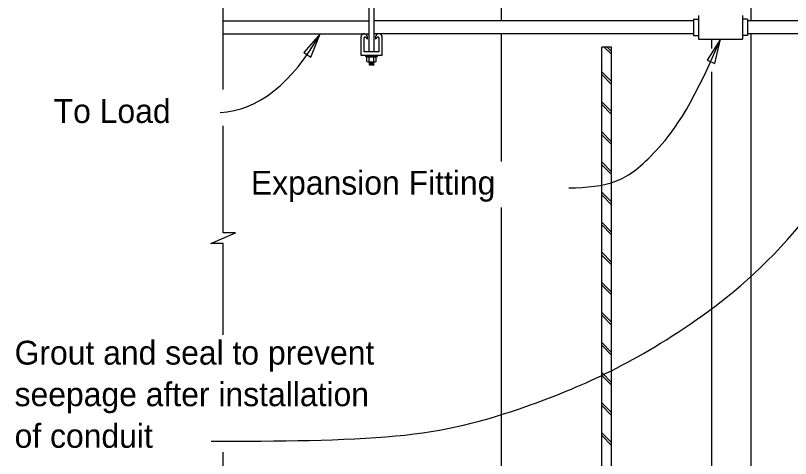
# Model space of a CAD drawing. Extents: x 0 to 30.8, y 0 to 21.2.
# Drawn here: x 21.338 to 26.255, y 4.02 to 6.831 of the extents above; entities that cross this region are included whole.
import ezdxf

# ---------------------------------------------------------------- set-up
doc = ezdxf.new("R2010")
doc.units = 0
for name, color, linetype in [('Dimension', 7, 'Continuous'), ('Lighting', 7, 'Continuous'), ('Miscellaneous', 7, 'Continuous'), ('SteelGirder', 7, 'Continuous'), ('TextStructures', 7, 'Continuous')]:
    doc.layers.add(name, color=color, linetype=linetype)

msp = doc.modelspace()

# ---------------------------------------------------------------- linework, layer by layer
at = {"layer": 'Dimension'}
for points in [[(22.6555, 6.3623), (22.6555, 8.629)], [(22.6555, 4.8062), (22.6555, 5.3851), (22.578, 5.3851), (22.6555, 5.4189), (22.733, 5.4526), (22.6555, 5.4526), (22.6555, 6.1316)], [(22.6555, 3.7827), (22.6555, 4.0614)]]:
    msp.add_lwpolyline(points, dxfattribs=at)
for points in [[(23.2708, 6.7148), (23.1664, 6.5957), (23.2114, 6.5679)], [(25.8105, 6.6815), (25.7251, 6.548), (25.7738, 6.5274)]]:
    msp.add_lwpolyline(points, close=True, dxfattribs=at)
msp.add_ellipse((22.5257, 8.5836), major_axis=(-0.1111, 2.3674), ratio=0.464296, start_param=3.141604, end_param=3.781059, dxfattribs=at)
for points in [[(22.5801, 4.1306), (23.0069, 4.1308), (23.8463, 4.1349), (24.524, 4.3118), (25.5501, 4.7344), (26.5058, 5.5697), (27.039, 6.6659)], [(24.8476, 5.7378), (24.9631, 5.7397), (25.1652, 5.7557), (25.3791, 5.9333), (25.6155, 6.2201), (25.8105, 6.6815)]]:
    msp.add_open_spline(points, degree=3, dxfattribs=at)
at = {"layer": 'Lighting'}
for p, q in [((22.6555, 6.798), (23.5813, 6.798)), ((25.6384, 6.798), (23.6125, 6.798)), ((25.6384, 6.8083), (25.6384, 6.7041)), ((25.6384, 6.8083), (25.6717, 6.8083)), ((25.6717, 6.8313), (25.6717, 6.6814)), ((25.9492, 6.8312), (25.9492, 6.6813)), ((25.9826, 6.8083), (25.9492, 6.8083)), ((25.9826, 6.8083), (25.9826, 6.7041)), ((29.0415, 6.7981), (25.9826, 6.7981)), ((22.6555, 6.7147), (23.5813, 6.7147)), ((23.5292, 6.6939), (23.5292, 6.5793)), ((23.55, 6.6001), (23.55, 6.6891)), ((23.5589, 6.6928), (23.5708, 6.6808)), ((23.5708, 6.6987), (23.5687, 6.7031)), ((23.5708, 6.6808), (23.5708, 6.6987)), ((25.6384, 6.7146), (23.6125, 6.7146)), ((23.6252, 6.7031), (23.623, 6.6987)), ((23.623, 6.6987), (23.623, 6.6808)), ((23.623, 6.6808), (23.6349, 6.6928)), ((23.6438, 6.6891), (23.6438, 6.6001)), ((23.6646, 6.5793), (23.6646, 6.6939)), ((25.6384, 6.7041), (25.6717, 6.7041)), ((25.9826, 6.7041), (25.9492, 6.7041)), ((29.0415, 6.7147), (25.9826, 6.7147)), ((25.6718, 6.6815), (25.9492, 6.6815)), ((23.6438, 6.6001), (23.55, 6.6001)), ((23.5292, 6.5793), (23.6646, 6.5793))]:
    msp.add_line(p, q, dxfattribs=at)
for centre, radius, start, end in [((23.55, 6.6939), 0.0208, 26.1794, 179.9999), ((23.5552, 6.6891), 0.0052, 45, 180), ((23.6438, 6.6939), 0.0208, 0.0001, 153.8206), ((23.6386, 6.6891), 0.0052, 360, 135)]:
    msp.add_arc(centre, radius, start, end, dxfattribs=at)
at = {"layer": 'Miscellaneous'}
for p, q in [((25.1192, 6.5854), (25.0732, 6.6314)), ((25.1192, 6.6031), (25.0909, 6.6314)), ((25.1192, 6.4122), (25.0568, 6.4746)), ((25.1192, 6.3945), (25.0568, 6.4569)), ((25.1192, 6.2213), (25.0568, 6.2837)), ((25.1192, 6.2036), (25.0568, 6.266)), ((25.1192, 6.0303), (25.0568, 6.0927)), ((25.1192, 6.0127), (25.0568, 6.0751)), ((25.1192, 5.8394), (25.0568, 5.9018)), ((25.1192, 5.8218), (25.0568, 5.8841)), ((25.1192, 5.6485), (25.0568, 5.7109)), ((25.1192, 5.6308), (25.0568, 5.6932)), ((25.1192, 5.4576), (25.0568, 5.52)), ((25.1192, 5.4399), (25.0568, 5.5023)), ((25.1192, 5.2667), (25.0568, 5.3291)), ((25.1192, 5.249), (25.0568, 5.3114)), ((25.1192, 5.0758), (25.0568, 5.1382)), ((25.1192, 5.0581), (25.0568, 5.1205)), ((25.1192, 4.8848), (25.0568, 4.9472)), ((25.1192, 4.8672), (25.0568, 4.9296)), ((25.1192, 4.6939), (25.0568, 4.7563)), ((25.1192, 4.6762), (25.0568, 4.7386)), ((25.1192, 4.503), (25.0568, 4.5654)), ((25.1192, 4.4853), (25.0568, 4.5477)), ((25.1192, 4.3121), (25.0568, 4.3745)), ((25.1192, 4.2944), (25.0568, 4.3568)), ((25.1192, 4.1212), (25.0568, 4.1836)), ((25.1192, 4.1035), (25.0568, 4.1659))]:
    msp.add_line(p, q, dxfattribs=at)
at = {"layer": 'SteelGirder'}
for p, q in [((23.5813, 6.6001), (23.5813, 7.6603)), ((23.6125, 6.6001), (23.6125, 7.6603)), ((26.0047, 6.7981), (26.0047, 7.5273)), ((24.4213, 6.798), (24.4213, 7.5041)), ((24.4213, 5.9056), (24.4213, 6.7147)), ((26.0047, 2.2465), (26.0047, 6.7147)), ((25.7547, 6.6227), (25.7547, 6.6815)), ((25.1191, 6.6314), (25.0567, 6.6314)), ((25.0568, 2.2465), (25.0568, 6.6314)), ((25.1192, 2.2465), (25.1192, 6.6314)), ((23.5668, 6.5398), (23.5668, 6.5682)), ((23.5668, 6.5682), (23.627, 6.5682)), ((23.5819, 6.5398), (23.5819, 6.5682)), ((23.6119, 6.5398), (23.6119, 6.5682)), ((23.627, 6.5398), (23.627, 6.5682)), ((23.5743, 6.5376), (23.6195, 6.5376)), ((23.5812, 6.537), (23.5878, 6.5376)), ((23.5812, 6.537), (23.5823, 6.5376)), ((23.5865, 6.5348), (23.5812, 6.537)), ((23.5812, 6.5318), (23.5865, 6.5348)), ((23.5812, 6.5318), (23.6125, 6.5345)), ((23.5865, 6.5296), (23.5812, 6.5318)), ((23.5812, 6.5266), (23.5865, 6.5296)), ((23.5812, 6.5266), (23.6125, 6.5293)), ((23.5865, 6.5244), (23.5812, 6.5266)), ((23.5812, 6.5214), (23.5865, 6.5244)), ((23.5812, 6.5214), (23.6125, 6.5241)), ((23.5865, 6.5192), (23.5812, 6.5214)), ((23.583, 6.5173), (23.5865, 6.5192)), ((23.5831, 6.5173), (23.6096, 6.5173)), ((23.5931, 6.5173), (23.6125, 6.5189)), ((23.6072, 6.5366), (23.6088, 6.5376)), ((23.6125, 6.5345), (23.6072, 6.5366)), ((23.6072, 6.5314), (23.6125, 6.5345)), ((23.6125, 6.5293), (23.6072, 6.5314)), ((23.6072, 6.5263), (23.6125, 6.5293)), ((23.6125, 6.5241), (23.6072, 6.5263)), ((23.6072, 6.521), (23.6125, 6.5241)), ((23.6125, 6.5189), (23.6072, 6.521)), ((23.6096, 6.5173), (23.6125, 6.5189)), ((25.7547, 2.2465), (25.7547, 6.4742)), ((24.4213, 2.2465), (24.4213, 5.6138))]:
    msp.add_line(p, q, dxfattribs=at)
msp.add_lwpolyline([(23.6322, 6.5793), (23.6322, 6.5682), (23.5616, 6.5682), (23.5616, 6.5793)], close=True, dxfattribs=at)
for centre, radius, start, end in [((23.5743, 6.5514), 0.0138, 236.9791, 303.0209), ((23.5969, 6.5894), 0.0519, 253.1396, 286.8604), ((23.6195, 6.5514), 0.0138, 236.9791, 303.0209)]:
    msp.add_arc(centre, radius, start, end, dxfattribs=at)

# ---------------------------------------------------------------- texts
at = {"layer": 'Dimension'}
for s, p in [('Grout and seal to prevent ', (21.3326, 4.6164)), ('seepage after installation ', (21.3326, 4.3524)), ('of conduit', (21.3326, 4.0884))]:
    msp.add_text(s, height=0.1512, dxfattribs=at).set_placement(p)
at = {"layer": 'TextStructures'}
for s, p in [('To Load', (21.5804, 6.1494)), ('Expansion Fitting', (22.8316, 5.6944))]:
    msp.add_text(s, height=0.1512, dxfattribs=at).set_placement(p)

doc.saveas('drawing.dxf')
